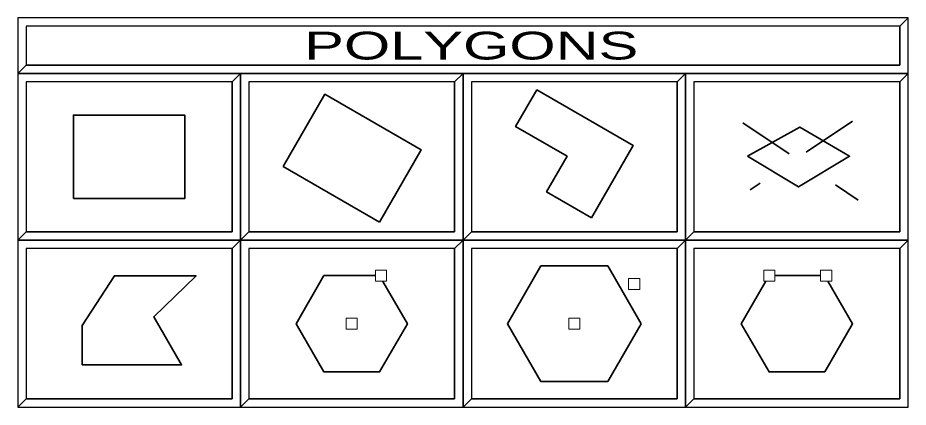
# Model space of a CAD drawing. Extents: x 95906.8 to 95923.6, y 90964.8 to 90972.8.
# Drawn here: x 95910.832 to 95912.432, y 90970.062 to 90970.762 of the extents above; entities that cross this region are included whole.
import ezdxf
from ezdxf.enums import TextEntityAlignment as Align

# ---------------------------------------------------------------- set-up
doc = ezdxf.new("R2010")
doc.units = 0
doc.header["$LTSCALE"] = 0.019
doc.linetypes.add('MEDIUM_DASHED', pattern=[4.5, 3, -1.5])
for name, color, linetype, lineweight in [('1', 7, 'Continuous', 25), ('11', 7, 'Continuous', 25), ('12', 7, 'Continuous', 25), ('17', 7, 'Continuous', 25), ('2', 7, 'Continuous', 13), ('3', 7, 'Continuous', 25), ('6', 7, 'Continuous', 35), ('7', 7, 'Continuous', 35)]:
    doc.layers.add(name, color=color, linetype=linetype, lineweight=lineweight)

msp = doc.modelspace()

# ---------------------------------------------------------------- linework, layer by layer
at = {"layer": '1'}
for points in [[(95910.8318, 90970.6617), (95912.4318, 90970.6617), (95912.4318, 90970.7617), (95910.8318, 90970.7617)], [(95910.8318, 90970.3617), (95911.2318, 90970.3617), (95911.2318, 90970.6617), (95910.8318, 90970.6617)], [(95911.2318, 90970.3617), (95911.6318, 90970.3617), (95911.6318, 90970.6617), (95911.2318, 90970.6617)], [(95911.6318, 90970.3617), (95912.0318, 90970.3617), (95912.0318, 90970.6617), (95911.6318, 90970.6617)], [(95912.0318, 90970.3617), (95912.4318, 90970.3617), (95912.4318, 90970.6617), (95912.0318, 90970.6617)], [(95910.8318, 90970.0617), (95911.2318, 90970.0617), (95911.2318, 90970.3617), (95910.8318, 90970.3617)], [(95911.2318, 90970.0617), (95911.6318, 90970.0617), (95911.6318, 90970.3617), (95911.2318, 90970.3617)], [(95911.6318, 90970.0617), (95912.0318, 90970.0617), (95912.0318, 90970.3617), (95911.6318, 90970.3617)], [(95912.0318, 90970.0617), (95912.4318, 90970.0617), (95912.4318, 90970.3617), (95912.0318, 90970.3617)]]:
    msp.add_lwpolyline(points, close=True, dxfattribs=at)
at = {"layer": '11'}
for points in [[(95911.2468, 90970.3767), (95911.6168, 90970.3767), (95911.6168, 90970.6467), (95911.2468, 90970.6467)], [(95911.6468, 90970.3767), (95912.0168, 90970.3767), (95912.0168, 90970.6467), (95911.6468, 90970.6467)], [(95912.0468, 90970.3767), (95912.4168, 90970.3767), (95912.4168, 90970.6467), (95912.0468, 90970.6467)], [(95910.8468, 90970.0767), (95911.2168, 90970.0767), (95911.2168, 90970.3467), (95910.8468, 90970.3467)], [(95911.2468, 90970.0767), (95911.6168, 90970.0767), (95911.6168, 90970.3467), (95911.2468, 90970.3467)], [(95911.6468, 90970.0767), (95912.0168, 90970.0767), (95912.0168, 90970.3467), (95911.6468, 90970.3467)], [(95912.0468, 90970.0767), (95912.4168, 90970.0767), (95912.4168, 90970.3467), (95912.0468, 90970.3467)]]:
    msp.add_lwpolyline(points, close=True, dxfattribs=at)
at = {"layer": '12'}
msp.add_lwpolyline([(95910.8468, 90970.3767), (95911.2168, 90970.3767), (95911.2168, 90970.6467), (95910.8468, 90970.6467)], close=True, dxfattribs=at)
at = {"layer": '17'}
msp.add_lwpolyline([(95910.8468, 90970.6767), (95912.4168, 90970.6767), (95912.4168, 90970.7467), (95910.8468, 90970.7467)], close=True, dxfattribs=at)
at = {"layer": '2'}
for points in [[(95910.8318, 90970.7617), (95910.8318, 90970.6617), (95910.8468, 90970.6767), (95910.8468, 90970.7467), (95912.4168, 90970.7467), (95912.4318, 90970.7617)], [(95910.8318, 90970.6617), (95910.8318, 90970.3617), (95910.8468, 90970.3767), (95910.8468, 90970.6467), (95911.2168, 90970.6467), (95911.2318, 90970.6617)], [(95911.2318, 90970.6617), (95911.2318, 90970.3617), (95911.2468, 90970.3767), (95911.2468, 90970.6467), (95911.6168, 90970.6467), (95911.6318, 90970.6617)], [(95911.6318, 90970.6617), (95911.6318, 90970.3617), (95911.6468, 90970.3767), (95911.6468, 90970.6467), (95912.0168, 90970.6467), (95912.0318, 90970.6617)], [(95912.0318, 90970.6617), (95912.0318, 90970.3617), (95912.0468, 90970.3767), (95912.0468, 90970.6467), (95912.4168, 90970.6467), (95912.4318, 90970.6617)], [(95910.8318, 90970.3617), (95910.8318, 90970.0617), (95910.8468, 90970.0767), (95910.8468, 90970.3467), (95911.2168, 90970.3467), (95911.2318, 90970.3617)], [(95911.2318, 90970.3617), (95911.2318, 90970.0617), (95911.2468, 90970.0767), (95911.2468, 90970.3467), (95911.6168, 90970.3467), (95911.6318, 90970.3617)], [(95911.6318, 90970.3617), (95911.6318, 90970.0617), (95911.6468, 90970.0767), (95911.6468, 90970.3467), (95912.0168, 90970.3467), (95912.0318, 90970.3617)], [(95912.0318, 90970.3617), (95912.0318, 90970.0617), (95912.0468, 90970.0767), (95912.0468, 90970.3467), (95912.4168, 90970.3467), (95912.4318, 90970.3617)]]:
    msp.add_lwpolyline(points, close=True, dxfattribs=at)
at = {"layer": '3'}
for points in [[(95910.8318, 90970.6617), (95912.4318, 90970.6617), (95912.4318, 90970.7617), (95912.4168, 90970.7467), (95912.4168, 90970.6767), (95910.8468, 90970.6767)], [(95910.8318, 90970.3617), (95911.2318, 90970.3617), (95911.2318, 90970.6617), (95911.2168, 90970.6467), (95911.2168, 90970.3767), (95910.8468, 90970.3767)], [(95911.2318, 90970.3617), (95911.6318, 90970.3617), (95911.6318, 90970.6617), (95911.6168, 90970.6467), (95911.6168, 90970.3767), (95911.2468, 90970.3767)], [(95911.6318, 90970.3617), (95912.0318, 90970.3617), (95912.0318, 90970.6617), (95912.0168, 90970.6467), (95912.0168, 90970.3767), (95911.6468, 90970.3767)], [(95912.0318, 90970.3617), (95912.4318, 90970.3617), (95912.4318, 90970.6617), (95912.4168, 90970.6467), (95912.4168, 90970.3767), (95912.0468, 90970.3767)], [(95910.8318, 90970.0617), (95911.2318, 90970.0617), (95911.2318, 90970.3617), (95911.2168, 90970.3467), (95911.2168, 90970.0767), (95910.8468, 90970.0767)], [(95911.2318, 90970.0617), (95911.6318, 90970.0617), (95911.6318, 90970.3617), (95911.6168, 90970.3467), (95911.6168, 90970.0767), (95911.2468, 90970.0767)], [(95911.6318, 90970.0617), (95912.0318, 90970.0617), (95912.0318, 90970.3617), (95912.0168, 90970.3467), (95912.0168, 90970.0767), (95911.6468, 90970.0767)], [(95912.0318, 90970.0617), (95912.4318, 90970.0617), (95912.4318, 90970.3617), (95912.4168, 90970.3467), (95912.4168, 90970.0767), (95912.0468, 90970.0767)]]:
    msp.add_lwpolyline(points, close=True, dxfattribs=at)
at = {"layer": '6', "linetype": 'MEDIUM_DASHED'}
for p, q in [((95912.1349, 90970.5731), (95912.3422, 90970.434)), ((95912.3317, 90970.5757), (95912.148, 90970.4524))]:
    msp.add_line(p, q, dxfattribs=at)
at = {"layer": '6'}
msp.add_line((95912.2746, 90970.2983), (95912.1929, 90970.2983), dxfattribs=at)
for points in [[(95911.4819, 90970.3944), (95911.3087, 90970.4944), (95911.3837, 90970.6243), (95911.5569, 90970.5243)], [(95911.8627, 90970.4021), (95911.9377, 90970.532), (95911.7645, 90970.632), (95911.7264, 90970.566), (95911.8188, 90970.5127), (95911.7819, 90970.4488)], [(95910.9318, 90970.4367), (95911.1318, 90970.4367), (95911.1318, 90970.5867), (95910.9318, 90970.5867)], [(95912.1428, 90970.5127), (95912.2372, 90970.5652), (95912.3264, 90970.5127), (95912.2346, 90970.4576)], [(95911.952, 90970.2117), (95911.8919, 90970.3158), (95911.7717, 90970.3158), (95911.7116, 90970.2117), (95911.7717, 90970.1076), (95911.8919, 90970.1076)], [(95910.9476, 90970.1378), (95910.9476, 90970.2087), (95911.0054, 90970.2979), (95911.1523, 90970.2979), (95911.0762, 90970.2244), (95911.126, 90970.1378)]]:
    msp.add_lwpolyline(points, close=True, dxfattribs=at)
at = {"layer": '6', "lineweight": 13}
for points in [[(95911.4743, 90970.2883), (95911.4943, 90970.2883), (95911.4943, 90970.3083), (95911.4743, 90970.3083)], [(95912.1722, 90970.2883), (95912.1922, 90970.2883), (95912.1922, 90970.3083), (95912.1722, 90970.3083)], [(95912.2745, 90970.2883), (95912.2945, 90970.2883), (95912.2945, 90970.3083), (95912.2745, 90970.3083)], [(95911.9294, 90970.2732), (95911.9494, 90970.2732), (95911.9494, 90970.2932), (95911.9294, 90970.2932)], [(95911.4218, 90970.2017), (95911.4418, 90970.2017), (95911.4418, 90970.2217), (95911.4218, 90970.2217)], [(95911.8218, 90970.2017), (95911.8418, 90970.2017), (95911.8418, 90970.2217), (95911.8218, 90970.2217)]]:
    msp.add_lwpolyline(points, close=True, dxfattribs=at)
at = {"layer": '6'}
for points in [[(95911.4742, 90970.2983), (95911.3818, 90970.2983), (95911.3318, 90970.2117), (95911.3818, 90970.1251), (95911.4818, 90970.1251), (95911.5318, 90970.2117), (95911.4879, 90970.2878)], [(95912.1761, 90970.2884), (95912.1318, 90970.2117), (95912.1818, 90970.1251), (95912.2818, 90970.1251), (95912.3318, 90970.2117), (95912.2876, 90970.2883)]]:
    msp.add_lwpolyline(points, dxfattribs=at)

# ---------------------------------------------------------------- texts
at = {"layer": '7', "width": 1.6}
msp.add_text('        POLYGONS       ', height=0.04999, dxfattribs=at).set_placement((95911.6318, 90970.6867), align=Align.CENTER)

doc.saveas('drawing.dxf')
